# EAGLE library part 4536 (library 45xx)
Programmable TIMER
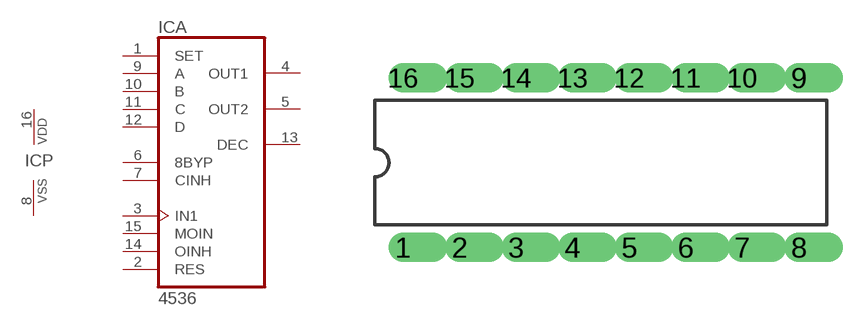
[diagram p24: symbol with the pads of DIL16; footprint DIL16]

Designator prefix IC; gates A=4536 P=PWRN

## 4536N  [DIL16]
1  A:SET  in
2  A:RES  in
3  A:IN1  in
4  A:OUT1  out
5  A:OUT2  out
6  A:8BYP  in
7  A:CINH  in
8  P:VSS  pwr
9  A:A  in
10  A:B  in
11  A:C  in
12  A:D  in
13  A:DEC  out
14  A:OINH  in
15  A:MOIN  in
16  P:VDD  pwr

## Footprint DIL16 (pad centres in mm)
Dual In Line
drill 0.813 offset: 1 -8.89,-3.81; 2 -6.35,-3.81; 3 -3.81,-3.81; 4 -1.27,-3.81; 5 1.27,-3.81; 6 3.81,-3.81; 7 6.35,-3.81; 8 8.89,-3.81; 9 8.89,3.81; 10 6.35,3.81; 11 3.81,3.81; 12 1.27,3.81; 13 -1.27,3.81; 14 -3.81,3.81; 15 -6.35,3.81; 16 -8.89,3.81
